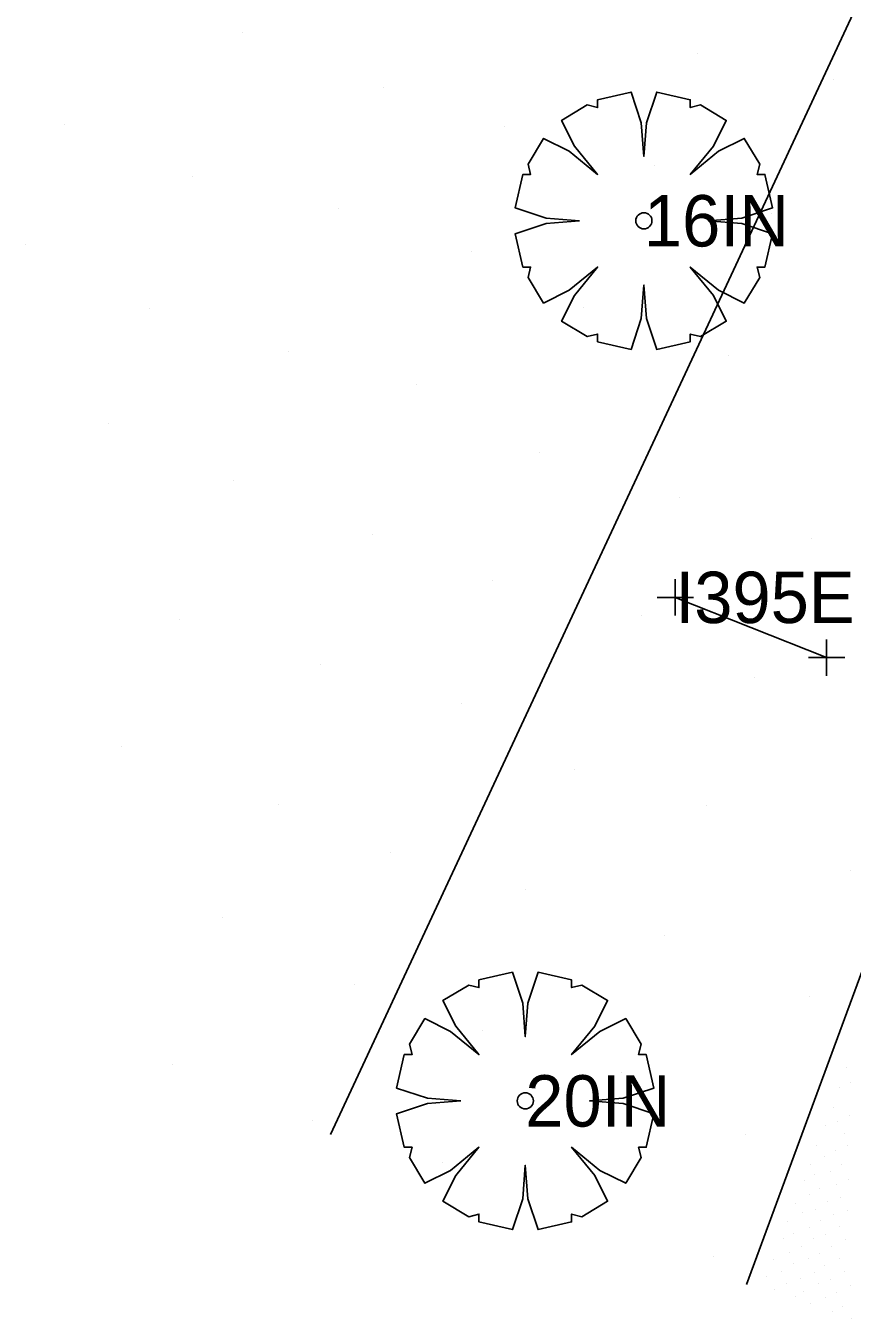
# Model space of a CAD drawing. Extents: x 1729983 to 1730242, y 468641 to 469019.
# Drawn here: x 1729987.57 to 1730016.54, y 468696.82 to 468742.12 of the extents above; entities that cross this region are included whole.
import ezdxf

# ---------------------------------------------------------------- set-up
doc = ezdxf.new("R2010")
doc.units = 0
for name, color, linetype in [('Default', 7, 'Continuous'), ('S_Ground_SpotElevation', 7, 'Continuous'), ('S_Roadway_Sidewalks', 7, 'Continuous'), ('S_Survey_Shot', 7, 'Continuous'), ('S_Text', 7, 'Continuous'), ('S_Traffic_Sign_DoublePost', 7, 'Continuous'), ('S_Trees_Decid_Pay', 7, 'Continuous'), ('S_Utilities_AG_Communications', 7, 'Continuous')]:
    doc.layers.add(name, color=color, linetype=linetype)

# ---------------------------------------------------------------- blocks, each defined once
blk = doc.blocks.new('POINT_DISPLAY')
at = {"layer": 'Default'}
blk.add_line((0, 0), (0, 0), dxfattribs=at)

msp = doc.modelspace()

# ---------------------------------------------------------------- linework, layer by layer
at = {"layer": 'S_Roadway_Sidewalks'}
msp.add_lwpolyline([(1730033.218, 468779.896), (1730040.852, 468776.278), (1730041.205, 468774.325), (1730039.473, 468769.232), (1730035.785, 468759.578), (1730031.436, 468748.602), (1730024.922, 468730.8), (1730019.096, 468714.972), (1730012.838, 468697.998)], dxfattribs=at)
at = {"layer": 'S_Survey_Shot'}
for p, q in [((1730010.336, 468721.449), (1730010.334, 468722.721)), ((1730009.699, 468722.084), (1730010.971, 468722.086)), ((1730010.335, 468722.085), (1730010.335, 468722.085)), ((1730015.642, 468719.339), (1730015.64, 468720.611)), ((1730015.005, 468719.974), (1730016.277, 468719.976)), ((1730015.641, 468719.975), (1730015.641, 468719.975))]:
    msp.add_line(p, q, dxfattribs=at)
at = {"layer": 'S_Traffic_Sign_DoublePost'}
msp.add_lwpolyline([(1730010.335, 468722.085), (1730015.641, 468719.975)], dxfattribs=at)
at = {"layer": 'S_Trees_Decid_Pay'}
for points in [[(1730006.982, 468735.284), (1730005.808, 468735.374), (1730004.725, 468735.735), (1730004.996, 468736.907), (1730005.267, 468736.907), (1730005.177, 468737.269), (1730005.718, 468738.171), (1730006.62, 468737.72), (1730007.613, 468736.907), (1730006.801, 468737.9), (1730006.35, 468738.803), (1730007.253, 468739.344), (1730007.613, 468739.254), (1730007.613, 468739.525), (1730008.786, 468739.795), (1730009.147, 468738.712), (1730009.237, 468737.54), (1730009.327, 468738.712), (1730009.688, 468739.795), (1730010.861, 468739.525), (1730010.861, 468739.254), (1730011.221, 468739.344), (1730012.124, 468738.803), (1730011.673, 468737.9), (1730010.861, 468736.907), (1730011.854, 468737.72), (1730012.756, 468738.171), (1730013.297, 468737.269), (1730013.207, 468736.907), (1730013.478, 468736.907), (1730013.749, 468735.735), (1730012.666, 468735.374), (1730011.492, 468735.284), (1730012.666, 468735.194), (1730013.749, 468734.832), (1730013.478, 468733.659), (1730013.207, 468733.659), (1730013.297, 468733.299), (1730012.756, 468732.397), (1730011.854, 468732.848), (1730010.861, 468733.659), (1730011.673, 468732.667), (1730012.124, 468731.765), (1730011.221, 468731.224), (1730010.861, 468731.314), (1730010.861, 468731.044), (1730009.688, 468730.773), (1730009.327, 468731.855), (1730009.237, 468733.029), (1730009.147, 468731.855), (1730008.786, 468730.773), (1730007.613, 468731.044), (1730007.613, 468731.314), (1730007.253, 468731.224), (1730006.35, 468731.765), (1730006.801, 468732.667), (1730007.613, 468733.659), (1730006.62, 468732.848), (1730005.718, 468732.397), (1730005.177, 468733.299), (1730005.267, 468733.659), (1730004.996, 468733.659), (1730004.725, 468734.832), (1730005.808, 468735.194), (1730006.982, 468735.284)], [(1730002.824, 468704.437), (1730001.65, 468704.527), (1730000.567, 468704.888), (1730000.838, 468706.06), (1730001.109, 468706.06), (1730001.019, 468706.422), (1730001.56, 468707.324), (1730002.462, 468706.873), (1730003.455, 468706.06), (1730002.643, 468707.053), (1730002.192, 468707.956), (1730003.095, 468708.497), (1730003.455, 468708.407), (1730003.455, 468708.678), (1730004.628, 468708.948), (1730004.989, 468707.865), (1730005.079, 468706.693), (1730005.169, 468707.865), (1730005.53, 468708.948), (1730006.703, 468708.678), (1730006.703, 468708.407), (1730007.063, 468708.497), (1730007.966, 468707.956), (1730007.515, 468707.053), (1730006.703, 468706.06), (1730007.696, 468706.873), (1730008.598, 468707.324), (1730009.139, 468706.422), (1730009.049, 468706.06), (1730009.32, 468706.06), (1730009.591, 468704.888), (1730008.508, 468704.527), (1730007.334, 468704.437), (1730008.508, 468704.347), (1730009.591, 468703.985), (1730009.32, 468702.812), (1730009.049, 468702.812), (1730009.139, 468702.452), (1730008.598, 468701.55), (1730007.696, 468702.001), (1730006.703, 468702.812), (1730007.515, 468701.82), (1730007.966, 468700.918), (1730007.063, 468700.377), (1730006.703, 468700.467), (1730006.703, 468700.197), (1730005.53, 468699.926), (1730005.169, 468701.008), (1730005.079, 468702.182), (1730004.989, 468701.008), (1730004.628, 468699.926), (1730003.455, 468700.197), (1730003.455, 468700.467), (1730003.095, 468700.377), (1730002.192, 468700.918), (1730002.643, 468701.82), (1730003.455, 468702.812), (1730002.462, 468702.001), (1730001.56, 468701.55), (1730001.019, 468702.452), (1730001.109, 468702.812), (1730000.838, 468702.812), (1730000.567, 468703.985), (1730001.65, 468704.347), (1730002.824, 468704.437)]]:
    msp.add_lwpolyline(points, dxfattribs=at)
for centre in [(1730009.237, 468735.284), (1730005.079, 468704.437)]:
    msp.add_circle(centre, 0.283, dxfattribs=at)
at = {"layer": 'S_Utilities_AG_Communications'}
msp.add_lwpolyline([(1730120.945, 469004.632), (1730097.184, 468954.408), (1730085.556, 468926.546), (1730082.304, 468910.964), (1730034.658, 468781.323), (1729998.254, 468703.261)], dxfattribs=at)

# ---------------------------------------------------------------- block references
at = {"layer": 'S_Ground_SpotElevation'}
for p in [(1729995.157, 468741.871), (1730011.126, 468741.162), (1730015.888, 468740.237), (1730000.122, 468739.969), (1729988.926, 468738.668), (1730004.338, 468738.597), (1730009.611, 468737.211), (1729993.409, 468736.849), (1729998.539, 468735.723), (1730013.705, 468735.553), (1729987.568, 468734.442), (1730003.184, 468734.211), (1729991.904, 468732.21), (1730007.118, 468732.249), (1729996.768, 468730.704), (1730012.198, 468730.568), (1730001.25, 468729.551), (1729990.462, 468728.177), (1730005.59, 468727.174), (1729994.842, 468726.184), (1730010.476, 468725.574), (1729999.718, 468724.283), (1730015.096, 468724.146), (1730003.942, 468722.68), (1729992.952, 468721.307), (1730009.169, 468721.462), (1729997.905, 468719.725), (1730013.118, 468719.276), (1730002.834, 468718.349), (1729990.905, 468716.863), (1730006.802, 468716.066), (1729996.439, 468714.813), (1730011.436, 468714.792), (1730000.345, 468713.147), (1730016.486, 468712.5), (1730005.07, 468711.832), (1729994.477, 468710.861), (1730009.961, 468710.227), (1729999.104, 468708.516), (1730015.06, 468708.099), (1730003.562, 468706.915), (1729992.716, 468705.724), (1730008.465, 468705.435), (1730016.353, 468705.595), (1730016.098, 468704.906), (1730016.471, 468705.091), (1730015.873, 468704.221), (1730016.45, 468703.908), (1729997.604, 468703.742), (1730015.616, 468703.59), (1730016.026, 468703.727), (1730012.782, 468703.246), (1730016.272, 468703.291), (1730015.281, 468702.875), (1730015.571, 468702.479), (1730015.947, 468702.681), (1730016.368, 468702.858), (1730002.182, 468702.294), (1730015.084, 468702.208), (1730016.148, 468702.213), (1730014.858, 468701.634), (1730015.227, 468701.848), (1730015.791, 468701.972), (1730016.404, 468701.671), (1730015.036, 468701.143), (1730015.407, 468701.351), (1730015.985, 468701.515), (1730014.548, 468700.855), (1730015.688, 468700.916), (1730016.131, 468701.051), (1730007.171, 468700.45), (1730014.262, 468700.211), (1730014.807, 468700.535), (1730015.265, 468700.63), (1730015.434, 468700.243), (1730015.885, 468700.455), (1730016.392, 468700.578), (1730014.495, 468699.801), (1730015.05, 468699.995), (1730015.604, 468699.75), (1730016.101, 468700.03), (1730014.126, 468699.6), (1730014.755, 468699.332), (1730015.167, 468699.614), (1730015.823, 468699.331), (1730016.292, 468699.562), (1730011.66, 468698.978), (1730013.787, 468698.863), (1730014.35, 468699.123), (1730015.011, 468698.927), (1730015.407, 468699.093), (1730016.088, 468698.909), (1730014.056, 468698.458), (1730014.494, 468698.73), (1730015.202, 468698.42), (1730015.553, 468698.663), (1730016.279, 468698.446), (1730013.542, 468698.281), (1730014.229, 468698.025), (1730014.731, 468698.224), (1730015.369, 468698.043), (1730015.769, 468698.187), (1730016.482, 468697.965), (1730013.814, 468697.833), (1730014.537, 468697.578), (1730014.844, 468697.764), (1730015.604, 468697.541), (1730015.978, 468697.709), (1730015.095, 468697.34), (1730015.837, 468697.038), (1730016.185, 468697.241), (1730016.52, 468696.822)]:
    msp.add_blockref('POINT_DISPLAY', p, dxfattribs=at)

# ---------------------------------------------------------------- texts
at = {"layer": 'S_Text'}
for s, p in [('16IN', (1730009.237, 468734.384)), ('I395E', (1730010.335, 468721.185)), ('20IN', (1730005.079, 468703.537))]:
    msp.add_text(s, height=1.8, dxfattribs=at).set_placement(p)

doc.saveas('drawing.dxf')
